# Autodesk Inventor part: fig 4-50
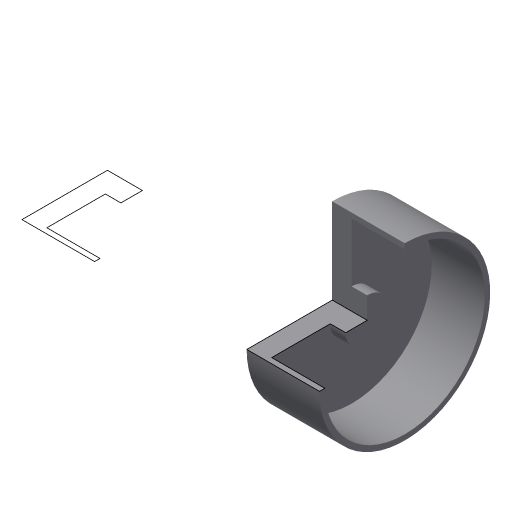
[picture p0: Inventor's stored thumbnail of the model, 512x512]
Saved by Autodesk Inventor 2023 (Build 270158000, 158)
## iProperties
Created: 2004-05
Part Number: fig 4-50
Document SubType Name: Modeling
Designer: CADCIM Technologies
Manufacturer: Standard
Standards Organization: Custom
Density: 1 g/cm^3
Material: Generic
Appearance: Default
Author: CADCIM Technologies
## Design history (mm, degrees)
sketch "Sketch1"
  geometry: L1 (30.083, 49.92)-(16.646, 49.92); L2 (16.646, 49.92)-(16.646, 17.104); L3 (16.646, 17.104)-(44.553, 17.104); L4 (44.553, 17.104)-(44.553, 19.171); L5 (44.553, 19.171)-(24.139, 19.171); L6 (24.139, 19.171)-(24.139, 41.652); L7 (24.139, 41.652)-(30.083, 41.652); L8 (30.083, 41.652)-(30.083, 49.92); L9 (116.437, 49.92)-(103, 49.92); L10 (103, 49.92)-(103, 17.104); L11 (103, 17.104)-(130.907, 17.104); L12 (130.907, 17.104)-(130.907, 19.171); L13 (130.907, 19.171)-(110.494, 19.171); L14 (110.494, 19.171)-(110.494, 41.652); L15 (110.494, 41.652)-(116.437, 41.652); L16 (116.437, 41.652)-(116.437, 49.92)
  constraints: 32 end point, 2 horizontal
revolve "Revolution1" sketch "Sketch1" stored, may be unused: angle "d0" = 270 deg
body "Solid1"
